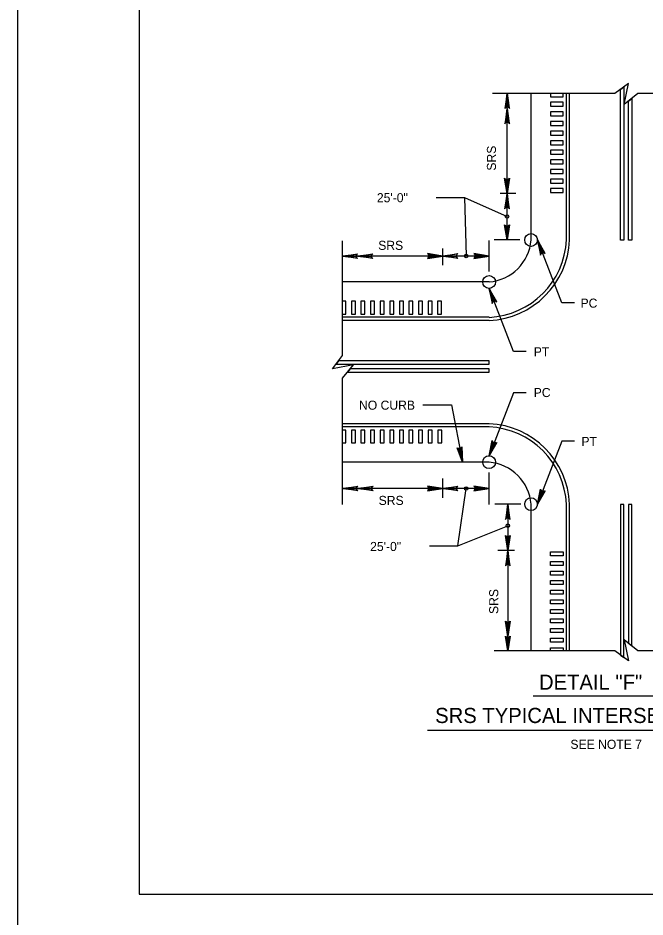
# Model space of a CAD drawing. Extents: x 632008 to 634206, y 294231 to 297795.
# Drawn here: x 632007.9 to 632215, y 296614.1 to 296911.1 of the extents above; entities that cross this region are included whole.
import ezdxf

# ---------------------------------------------------------------- set-up
doc = ezdxf.new("R2010")
doc.units = 0
for name, color, linetype in [('1', 7, 'Continuous'), ('Level 2', 7, 'Continuous'), ('PLT-BNDY', 7, 'Continuous')]:
    doc.layers.add(name, color=color, linetype=linetype)

msp = doc.modelspace()

# ---------------------------------------------------------------- linework, layer by layer
at = {"layer": '1'}
for p, q in [((632178.07, 296687.2), (632229.83, 296687.2)), ((632143.19, 296675.83), (632266.7, 296675.83))]:
    msp.add_line(p, q, dxfattribs=at)
msp.add_lwpolyline([(632833.86, 296621.62), (632833.86, 297185.62), (632047.86, 297185.62), (632047.86, 296621.62), (632833.86, 296621.62), (632833.86, 296647.98), (632633.86, 296647.98), (632633.86, 296712.66), (632833.86, 296712.66), (632833.86, 296741.62), (632633.86, 296741.62), (632633.86, 296621.62), (632712.66, 296621.62), (632712.66, 296647.98), (632712.66, 296621.62), (632789.66, 296621.62), (632789.66, 296647.98), (632789.66, 296635.66), (632833.86, 296635.66)], dxfattribs=at)
for points in [[(632208, 296888.33), (632208, 296837.76), (632206.95, 296837.76), (632206.95, 296887.54)], [(632210.64, 296884.49), (632210.64, 296837.76), (632209.58, 296837.76), (632209.58, 296883.63)], [(632112.96, 296796.77), (632163.52, 296796.77), (632163.52, 296797.83), (632113.75, 296797.83)], [(632116.79, 296794.13), (632163.52, 296794.13), (632163.52, 296795.19), (632117.66, 296795.19)], [(632208, 296699.86), (632208, 296750.43), (632206.95, 296750.43), (632206.95, 296700.65)], [(632210.64, 296703.7), (632210.64, 296750.43), (632209.58, 296750.43), (632209.58, 296704.56)]]:
    msp.add_lwpolyline(points, close=True, dxfattribs=at)
at = {"layer": 'Level 2'}
for p, q in [((632209.54, 296889.48), (632205.11, 296886.16)), ((632208.2, 296882.51), (632209.54, 296889.48)), ((632205.11, 296886.16), (632164.67, 296886.16)), ((632169.46, 296837.78), (632169.5, 296886.24)), ((632177.41, 296837.78), (632177.41, 296886.16)), ((632189.06, 296837.78), (632189.06, 296886.16)), ((632190.12, 296837.78), (632190.12, 296886.16)), ((632212.7, 296886.16), (632208.2, 296882.51)), ((632249.9, 296886.16), (632212.7, 296886.16)), ((632155.45, 296851.78), (632169.48, 296845.49)), ((632172.31, 296853.11), (632167.16, 296853.11)), ((632115.13, 296799.66), (632115.12, 296837.46)), ((632163.54, 296827.36), (632163.54, 296837.6)), ((632173.73, 296837.78), (632165.18, 296837.78)), ((632148.21, 296829.41), (632148.21, 296835.02)), ((632163.54, 296832.48), (632115.05, 296832.46)), ((632163.54, 296823.91), (632115.12, 296823.91)), ((632163.54, 296812.26), (632115.12, 296812.26)), ((632163.54, 296811.2), (632115.12, 296811.2)), ((632111.81, 296795.23), (632115.13, 296799.66)), ((632118.77, 296796.58), (632111.81, 296795.23)), ((632115.13, 296792.08), (632118.77, 296796.58)), ((632115.13, 296750.44), (632115.13, 296792.08)), ((632163.54, 296777.08), (632115.13, 296777.08)), ((632163.54, 296776.03), (632115.13, 296776.03)), ((632163.54, 296764.38), (632115.13, 296764.38)), ((632163.54, 296750.44), (632163.54, 296760.95)), ((632148.21, 296752.57), (632148.21, 296759)), ((632163.54, 296755.7), (632115.15, 296755.7)), ((632153.24, 296736.77), (632155.97, 296755.7)), ((632174, 296750.51), (632165.39, 296750.51)), ((632169.7, 296750.51), (632169.7, 296702.03)), ((632177.41, 296702.03), (632177.41, 296750.51)), ((632189.06, 296702.03), (632189.06, 296750.51)), ((632190.12, 296702.03), (632190.12, 296750.51)), ((632171.94, 296735.17), (632166.39, 296735.17)), ((632212.7, 296702.03), (632208.2, 296705.68)), ((632208.2, 296705.68), (632209.54, 296698.71)), ((632205.11, 296702.03), (632165.17, 296702.03)), ((632209.54, 296698.71), (632205.11, 296702.03)), ((632250.58, 296702.03), (632212.7, 296702.03))]:
    msp.add_line(p, q, dxfattribs=at)
for points in [[(632170.11, 296881.44), (632169.76, 296881.62), (632169.5, 296886.24), (632170.11, 296881.44), (632170.32, 296881.2), (632169.5, 296886.24), (632169.28, 296881.63), (632168.93, 296881.46), (632169.5, 296886.24), (632168.7, 296881.2), (632168.93, 296881.46)], [(632183.77, 296886.16), (632183.77, 296885.1), (632187.99, 296885.1), (632187.99, 296886.16)], [(632170.11, 296876.42), (632169.76, 296876.6), (632169.5, 296881.22), (632170.11, 296876.42), (632170.32, 296876.18), (632169.5, 296881.22), (632169.28, 296876.61), (632168.93, 296876.44), (632169.5, 296881.22), (632168.7, 296876.18), (632168.93, 296876.44)], [(632170.08, 296857.91), (632169.73, 296857.73), (632169.47, 296853.11), (632170.08, 296857.91), (632170.29, 296858.15), (632169.47, 296853.11), (632169.24, 296857.73), (632168.9, 296857.9), (632169.47, 296853.11), (632168.67, 296858.15), (632168.9, 296857.9)], [(632146.03, 296851.78), (632155.45, 296851.78), (632155.91, 296832.5)], [(632170.06, 296848.32), (632169.71, 296848.5), (632169.46, 296853.11), (632170.06, 296848.32), (632170.27, 296848.07), (632169.46, 296853.11), (632169.23, 296848.5), (632168.89, 296848.33), (632169.46, 296853.11), (632168.66, 296848.07), (632168.89, 296848.33)], [(632170.06, 296842.57), (632169.71, 296842.39), (632169.46, 296837.78), (632170.06, 296842.57), (632170.27, 296842.82), (632169.46, 296837.78), (632169.23, 296842.39), (632168.89, 296842.56), (632169.46, 296837.78), (632168.66, 296842.82), (632168.89, 296842.56)], [(632191.74, 296816.97), (632187.52, 296816.97), (632179.52, 296837.78)], [(632181.76, 296833.49), (632181.37, 296833.54), (632179.52, 296837.78), (632181.76, 296833.49), (632182.04, 296833.33), (632179.52, 296837.78), (632180.92, 296833.37), (632180.66, 296833.1), (632179.52, 296837.78), (632180.53, 296832.77), (632180.66, 296833.1)], [(632119.84, 296831.86), (632119.67, 296832.21), (632115.05, 296832.46), (632119.84, 296831.86), (632120.09, 296831.65), (632115.05, 296832.46), (632119.66, 296832.69), (632119.83, 296833.03), (632115.05, 296832.46), (632120.09, 296833.26), (632119.83, 296833.03)], [(632124.86, 296831.86), (632124.69, 296832.21), (632120.07, 296832.46), (632124.86, 296831.86), (632125.11, 296831.65), (632120.07, 296832.46), (632124.68, 296832.69), (632124.85, 296833.03), (632120.07, 296832.46), (632125.11, 296833.26), (632124.85, 296833.03)], [(632143.41, 296831.88), (632143.59, 296832.23), (632148.21, 296832.48), (632143.41, 296831.88), (632143.17, 296831.67), (632148.21, 296832.48), (632143.59, 296832.71), (632143.42, 296833.05), (632148.21, 296832.48), (632143.17, 296833.28), (632143.42, 296833.05)], [(632153, 296831.88), (632152.82, 296832.23), (632148.21, 296832.48), (632153, 296831.88), (632153.25, 296831.67), (632148.21, 296832.48), (632152.82, 296832.71), (632152.99, 296833.05), (632148.21, 296832.48), (632153.25, 296833.28), (632152.99, 296833.05)], [(632158.75, 296831.88), (632158.93, 296832.23), (632163.54, 296832.48), (632158.75, 296831.88), (632158.5, 296831.67), (632163.54, 296832.48), (632158.93, 296832.71), (632158.76, 296833.05), (632163.54, 296832.48), (632158.5, 296833.28), (632158.76, 296833.05)], [(632165.78, 296817.51), (632165.39, 296817.56), (632163.54, 296821.8), (632165.78, 296817.51), (632166.06, 296817.35), (632163.54, 296821.8), (632164.94, 296817.39), (632164.68, 296817.12), (632163.54, 296821.8), (632164.55, 296816.79), (632164.68, 296817.12)], [(632175.76, 296800.99), (632171.54, 296800.99), (632163.54, 296821.8)], [(632115.12, 296813.33), (632116.18, 296813.33), (632116.18, 296817.55), (632115.12, 296817.55)], [(632175.76, 296787.3), (632171.54, 296787.3), (632163.54, 296766.49)], [(632141.64, 296783.27), (632151.05, 296783.27), (632154.75, 296764.38)], [(632115.13, 296770.73), (632116.19, 296770.73), (632116.19, 296774.95), (632115.13, 296774.95)], [(632165.78, 296770.77), (632165.39, 296770.73), (632163.54, 296766.49), (632165.78, 296770.77), (632166.06, 296770.93), (632163.54, 296766.49), (632164.94, 296770.89), (632164.68, 296771.17), (632163.54, 296766.49), (632164.55, 296771.49), (632164.68, 296771.17)], [(632191.74, 296771.32), (632187.52, 296771.32), (632179.52, 296750.51)], [(632154.4, 296769.19), (632154.09, 296768.96), (632154.75, 296764.38), (632154.4, 296769.19), (632154.56, 296769.48), (632154.75, 296764.38), (632153.62, 296768.85), (632153.25, 296768.95), (632154.75, 296764.38), (632152.97, 296769.16), (632153.25, 296768.95)], [(632119.94, 296755.09), (632119.77, 296755.44), (632115.15, 296755.7), (632119.94, 296755.09), (632120.19, 296754.88), (632115.15, 296755.7), (632119.76, 296755.92), (632119.93, 296756.26), (632115.15, 296755.7), (632120.19, 296756.5), (632119.93, 296756.26)], [(632124.96, 296755.09), (632124.79, 296755.44), (632120.17, 296755.7), (632124.96, 296755.09), (632125.21, 296754.88), (632120.17, 296755.7), (632124.78, 296755.92), (632124.95, 296756.26), (632120.17, 296755.7), (632125.21, 296756.5), (632124.95, 296756.26)], [(632143.41, 296755.09), (632143.59, 296755.44), (632148.21, 296755.7), (632143.41, 296755.09), (632143.17, 296754.88), (632148.21, 296755.7), (632143.59, 296755.92), (632143.43, 296756.26), (632148.21, 296755.7), (632143.17, 296756.5), (632143.43, 296756.26)], [(632153, 296755.09), (632152.82, 296755.44), (632148.21, 296755.7), (632153, 296755.09), (632153.25, 296754.88), (632148.21, 296755.7), (632152.82, 296755.92), (632152.99, 296756.26), (632148.21, 296755.7), (632153.25, 296756.5), (632152.99, 296756.26)], [(632158.75, 296755.09), (632158.93, 296755.44), (632163.54, 296755.7), (632158.75, 296755.09), (632158.5, 296754.88), (632163.54, 296755.7), (632158.93, 296755.92), (632158.76, 296756.26), (632163.54, 296755.7), (632158.5, 296756.5), (632158.76, 296756.26)], [(632181.76, 296754.79), (632181.37, 296754.75), (632179.52, 296750.51), (632181.76, 296754.79), (632182.04, 296754.95), (632179.52, 296750.51), (632180.92, 296754.91), (632180.66, 296755.19), (632179.52, 296750.51), (632180.53, 296755.51), (632180.66, 296755.19)], [(632170.3, 296745.71), (632169.95, 296745.89), (632169.7, 296750.51), (632170.3, 296745.71), (632170.51, 296745.47), (632169.7, 296750.51), (632169.47, 296745.89), (632169.13, 296745.72), (632169.7, 296750.51), (632168.9, 296745.47), (632169.13, 296745.72)], [(632143.82, 296736.77), (632153.24, 296736.77), (632169.72, 296743.33)], [(632170.3, 296739.96), (632169.95, 296739.79), (632169.7, 296735.17), (632170.3, 296739.96), (632170.51, 296740.21), (632169.7, 296735.17), (632169.47, 296739.78), (632169.13, 296739.95), (632169.7, 296735.17), (632168.9, 296740.21), (632169.13, 296739.95)], [(632170.3, 296730.37), (632169.95, 296730.55), (632169.7, 296735.17), (632170.3, 296730.37), (632170.51, 296730.13), (632169.7, 296735.17), (632169.47, 296730.56), (632169.13, 296730.39), (632169.7, 296735.17), (632168.9, 296730.13), (632169.13, 296730.39)], [(632170.31, 296711.63), (632169.96, 296711.45), (632169.7, 296706.84), (632170.31, 296711.63), (632170.51, 296711.88), (632169.7, 296706.84), (632169.47, 296711.45), (632169.13, 296711.62), (632169.7, 296706.84), (632168.9, 296711.88), (632169.13, 296711.62)], [(632170.31, 296706.62), (632169.96, 296706.45), (632169.7, 296702.03), (632170.31, 296706.62), (632170.51, 296706.86), (632169.7, 296702.03), (632169.47, 296706.45), (632169.13, 296706.61), (632169.7, 296702.03), (632168.9, 296706.86), (632169.13, 296706.61)], [(632183.77, 296702.03), (632183.77, 296703.09), (632187.99, 296703.09), (632187.99, 296702.03)]]:
    msp.add_lwpolyline(points, dxfattribs=at)
for points in [[(632187.99, 296881.94), (632187.99, 296883.26), (632183.77, 296883.26), (632183.77, 296881.94)], [(632187.99, 296878.77), (632187.99, 296880.09), (632183.77, 296880.09), (632183.77, 296878.77)], [(632187.99, 296875.6), (632187.99, 296876.92), (632183.77, 296876.92), (632183.77, 296875.6)], [(632187.99, 296872.44), (632187.99, 296873.76), (632183.77, 296873.76), (632183.77, 296872.44)], [(632187.99, 296869.27), (632187.99, 296870.59), (632183.77, 296870.59), (632183.77, 296869.27)], [(632187.99, 296866.1), (632187.99, 296867.42), (632183.77, 296867.42), (632183.77, 296866.1)], [(632187.99, 296862.94), (632187.99, 296864.26), (632183.77, 296864.26), (632183.77, 296862.94)], [(632187.99, 296859.77), (632187.99, 296861.09), (632183.77, 296861.09), (632183.77, 296859.77)], [(632187.99, 296856.6), (632187.99, 296857.92), (632183.77, 296857.92), (632183.77, 296856.6)], [(632187.99, 296853.44), (632187.99, 296854.75), (632183.77, 296854.75), (632183.77, 296853.44)], [(632118.03, 296813.33), (632119.35, 296813.33), (632119.35, 296817.55), (632118.03, 296817.55)], [(632121.2, 296813.33), (632122.52, 296813.33), (632122.52, 296817.55), (632121.2, 296817.55)], [(632124.37, 296813.33), (632125.68, 296813.33), (632125.68, 296817.55), (632124.37, 296817.55)], [(632127.53, 296813.33), (632128.85, 296813.33), (632128.85, 296817.55), (632127.53, 296817.55)], [(632130.7, 296813.33), (632132.02, 296813.33), (632132.02, 296817.55), (632130.7, 296817.55)], [(632133.87, 296813.33), (632135.19, 296813.33), (632135.19, 296817.55), (632133.87, 296817.55)], [(632137.03, 296813.33), (632138.35, 296813.33), (632138.35, 296817.55), (632137.03, 296817.55)], [(632140.2, 296813.33), (632141.52, 296813.33), (632141.52, 296817.55), (632140.2, 296817.55)], [(632143.37, 296813.33), (632144.69, 296813.33), (632144.69, 296817.55), (632143.37, 296817.55)], [(632146.53, 296813.33), (632147.85, 296813.33), (632147.85, 296817.55), (632146.53, 296817.55)], [(632118.03, 296770.73), (632119.35, 296770.73), (632119.35, 296774.95), (632118.03, 296774.95)], [(632121.2, 296770.73), (632122.52, 296770.73), (632122.52, 296774.95), (632121.2, 296774.95)], [(632124.37, 296770.73), (632125.69, 296770.73), (632125.69, 296774.95), (632124.37, 296774.95)], [(632127.53, 296770.73), (632128.85, 296770.73), (632128.85, 296774.95), (632127.53, 296774.95)], [(632130.7, 296770.73), (632132.02, 296770.73), (632132.02, 296774.95), (632130.7, 296774.95)], [(632133.87, 296770.73), (632135.19, 296770.73), (632135.19, 296774.95), (632133.87, 296774.95)], [(632137.04, 296770.73), (632138.35, 296770.73), (632138.35, 296774.95), (632137.04, 296774.95)], [(632140.2, 296770.73), (632141.52, 296770.73), (632141.52, 296774.95), (632140.2, 296774.95)], [(632143.37, 296770.73), (632144.69, 296770.73), (632144.69, 296774.95), (632143.37, 296774.95)], [(632146.54, 296770.73), (632147.86, 296770.73), (632147.86, 296774.95), (632146.54, 296774.95)], [(632187.99, 296734.75), (632187.99, 296733.43), (632183.77, 296733.43), (632183.77, 296734.75)], [(632187.99, 296731.59), (632187.99, 296730.27), (632183.77, 296730.27), (632183.77, 296731.59)], [(632187.99, 296728.42), (632187.99, 296727.1), (632183.77, 296727.1), (632183.77, 296728.42)], [(632187.99, 296725.25), (632187.99, 296723.93), (632183.77, 296723.93), (632183.77, 296725.25)], [(632187.99, 296722.09), (632187.99, 296720.77), (632183.77, 296720.77), (632183.77, 296722.09)], [(632187.99, 296718.92), (632187.99, 296717.6), (632183.77, 296717.6), (632183.77, 296718.92)], [(632187.99, 296715.75), (632187.99, 296714.43), (632183.77, 296714.43), (632183.77, 296715.75)], [(632187.99, 296712.59), (632187.99, 296711.27), (632183.77, 296711.27), (632183.77, 296712.59)], [(632187.99, 296709.42), (632187.99, 296708.1), (632183.77, 296708.1), (632183.77, 296709.42)], [(632187.99, 296706.25), (632187.99, 296704.93), (632183.77, 296704.93), (632183.77, 296706.25)]]:
    msp.add_lwpolyline(points, close=True, dxfattribs=at)
for centre, radius in [((632169.47, 296845.53), 0.581), ((632177.41, 296837.78), 2.11), ((632155.97, 296832.5), 0.581), ((632163.54, 296823.91), 2.11), ((632163.54, 296764.38), 2.11), ((632155.97, 296755.7), 0.581), ((632177.41, 296750.51), 2.11), ((632169.71, 296743.38), 0.581)]:
    msp.add_circle(centre, radius, dxfattribs=at)
for centre, radius, start, end in [((632162.26, 296839.06), 26.86, 272.6354, 357.3646), ((632162.26, 296839.06), 15.21, 274.837, 355.163), ((632162.26, 296839.06), 27.91, 272.6354, 357.3646), ((632162.26, 296749.22), 26.86, 2.6354, 87.3646), ((632162.26, 296749.22), 27.91, 2.6354, 87.3646), ((632162.26, 296749.22), 15.21, 4.837, 85.163)]:
    msp.add_arc(centre, radius, start, end, dxfattribs=at)
at = {"layer": 'PLT-BNDY'}
msp.add_lwpolyline([(632007.86, 297200.62), (632848.86, 297200.62), (632848.86, 296606.62), (632007.86, 296606.62)], close=True, dxfattribs=at)

# ---------------------------------------------------------------- texts
at = {"layer": 'Level 2'}
for p in [(632165.8, 296860.69), (632166.55, 296714.23)]:
    msp.add_text('SRS', height=3, rotation=90, dxfattribs=at).set_placement(p)
for s, height, p in [('25\'-0"', 3, (632126.46, 296850.25)), ('SRS', 3, (632126.89, 296834.51)), ('PC', 3, (632193.74, 296815.42)), ('PT', 3, (632178.27, 296799.35)), ('PC', 3, (632178.27, 296785.89)), ('NO CURB', 3, (632120.54, 296781.71)), ('PT', 3, (632194.04, 296769.72)), ('SRS', 3, (632127.03, 296750.25)), ('25\'-0"', 3, (632124.23, 296735.03)), ('DETAIL "F"', 5, (632180.01, 296689.21)), ('SRS TYPICAL INTERSECTION', 5, (632145.7, 296678.21)), ('SEE NOTE 7', 3, (632190.4, 296669.68))]:
    msp.add_text(s, height=height, dxfattribs=at).set_placement(p)

doc.saveas('drawing.dxf')
